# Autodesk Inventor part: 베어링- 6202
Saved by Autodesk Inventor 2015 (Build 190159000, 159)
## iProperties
Created: 2025-08
Part Number: 베어링- 6202
Material: 일반
Document SubType Name: Modeling
Designer: user
Density: 1 g/cm^3
Appearance: 기본값
Author: user
Author: jhkim
Description: 깊은 그루브 볼 베어링
Creation Date: 2025-08-05
Sending System: Autodesk Inventor 2026
Preprocessor: ST-DEVELOPER v20.1
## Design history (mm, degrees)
node "베어링- 62021"
body "Solid1"
node "Solid1_1"
node "Solid1_2"
node "Solid1_3"
node "Solid1_4"
node "Solid1_5"
node "Solid1_6"
node "Solid1_7"
node "Solid1_8"
node "Solid1_9"
node "기준1"
node "기준2"
node "기준3"
node "기준4"
node "기준5"
node "기준6"
node "기준7"
node "기준8"
node "기준9"
node "기준10"
